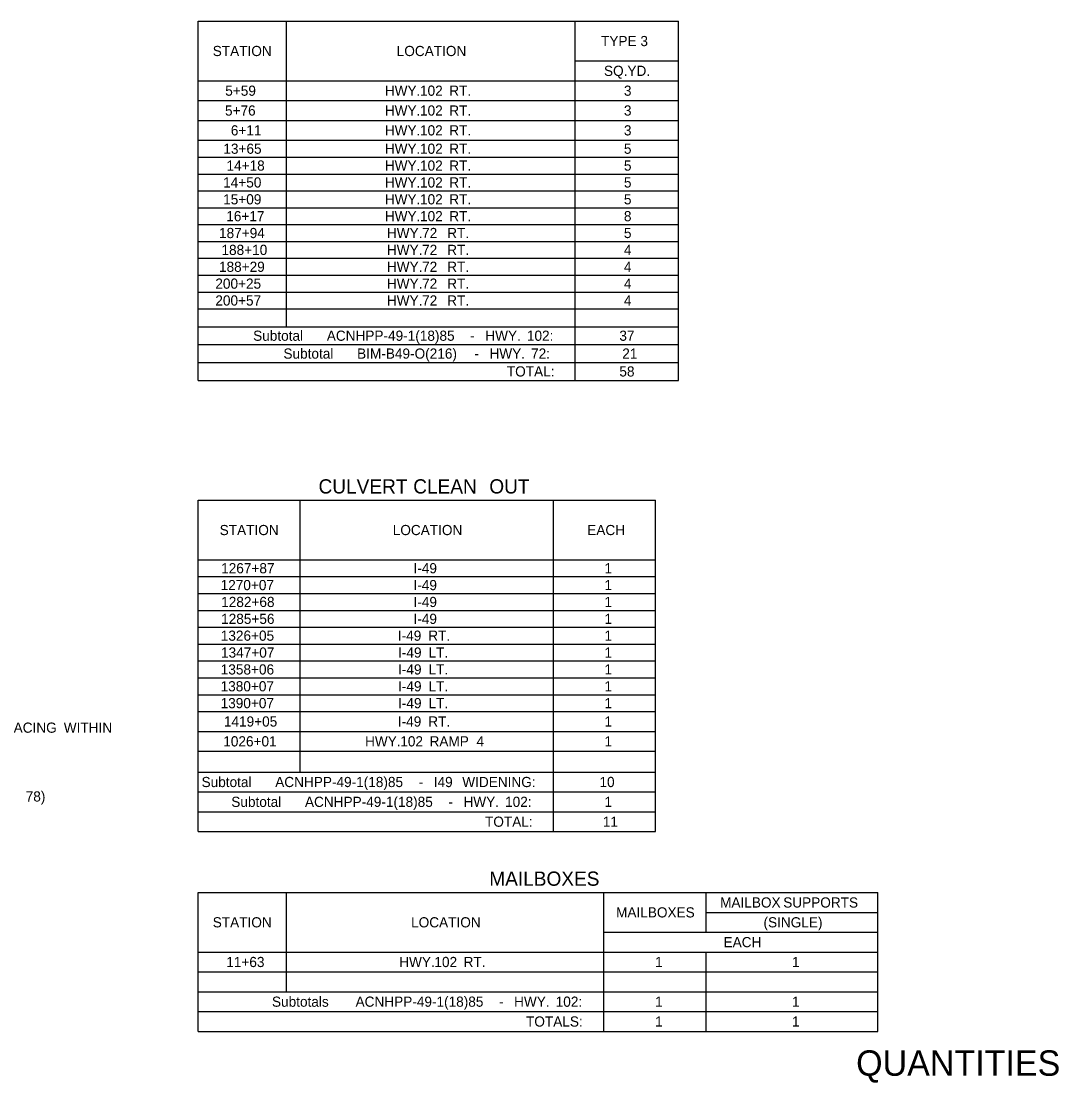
# Model space of a CAD drawing. Extents: x 1226605 to 1228152, y 151309 to 152316.
# Drawn here: x 1227621 to 1228130, y 151309 to 151831 of the extents above; entities that cross this region are included whole.
import ezdxf

# ---------------------------------------------------------------- set-up
doc = ezdxf.new("R2010")
doc.units = 0
doc.layers.add('R_Border Notes', color=7, linetype='Continuous')
doc.layers.add('R_Dimension', color=7, linetype='Continuous')

msp = doc.modelspace()

# ---------------------------------------------------------------- linework, layer by layer
at = {"layer": 'R_Dimension'}
for p, q in [((1227707.52, 151831.05), (1227943.47, 151831.05)), ((1227707.52, 151654.57), (1227707.52, 151831.05)), ((1227750.91, 151680.9), (1227750.91, 151831.05)), ((1227892.77, 151654.57), (1227892.77, 151831.05)), ((1227943.47, 151654.57), (1227943.47, 151831.05)), ((1227892.77, 151811.55), (1227943.47, 151811.55)), ((1227707.52, 151801.8), (1227943.47, 151801.8)), ((1227707.52, 151792.05), (1227943.47, 151792.05)), ((1227707.52, 151782.3), (1227943.47, 151782.3)), ((1227707.52, 151772.55), (1227943.47, 151772.55)), ((1227707.52, 151764.26), (1227943.47, 151764.26)), ((1227707.52, 151755.97), (1227943.47, 151755.97)), ((1227707.52, 151747.68), (1227943.47, 151747.68)), ((1227707.52, 151739.4), (1227943.47, 151739.4)), ((1227707.52, 151731.11), (1227943.47, 151731.11)), ((1227707.52, 151722.82), (1227943.47, 151722.82)), ((1227707.52, 151714.53), (1227943.47, 151714.53)), ((1227707.52, 151706.25), (1227943.47, 151706.25)), ((1227707.52, 151697.96), (1227943.47, 151697.96)), ((1227707.52, 151689.67), (1227943.47, 151689.67)), ((1227707.52, 151680.9), (1227943.47, 151680.9)), ((1227707.52, 151672.12), (1227943.47, 151672.12)), ((1227707.52, 151663.35), (1227943.47, 151663.35)), ((1227707.52, 151654.57), (1227943.47, 151654.57)), ((1227707.52, 151595.64), (1227932.26, 151595.64)), ((1227707.52, 151432.81), (1227707.52, 151595.64)), ((1227757.73, 151462.06), (1227757.73, 151595.64)), ((1227882.04, 151432.81), (1227882.04, 151595.64)), ((1227932.26, 151432.81), (1227932.26, 151595.64)), ((1227707.52, 151566.39), (1227932.26, 151566.39)), ((1227707.52, 151558.1), (1227932.26, 151558.1)), ((1227707.52, 151549.81), (1227932.26, 151549.81)), ((1227707.52, 151541.53), (1227932.26, 151541.53)), ((1227707.52, 151533.24), (1227932.26, 151533.24)), ((1227707.52, 151524.95), (1227932.26, 151524.95)), ((1227707.52, 151516.66), (1227932.26, 151516.66)), ((1227707.52, 151508.38), (1227932.26, 151508.38)), ((1227707.52, 151500.09), (1227932.26, 151500.09)), ((1227707.52, 151491.8), (1227932.26, 151491.8)), ((1227707.52, 151482.05), (1227932.26, 151482.05)), ((1227707.52, 151472.3), (1227932.26, 151472.3)), ((1227707.52, 151462.06), (1227932.26, 151462.06)), ((1227707.52, 151452.31), (1227932.26, 151452.31)), ((1227707.52, 151442.56), (1227932.26, 151442.56)), ((1227707.52, 151432.81), (1227932.26, 151432.81)), ((1227707.52, 151402.87), (1228041.46, 151402.87)), ((1227707.52, 151334.62), (1227707.52, 151402.87)), ((1227750.91, 151354.12), (1227750.91, 151402.87)), ((1227906.91, 151334.62), (1227906.91, 151402.87)), ((1227957.12, 151383.37), (1227957.12, 151402.87)), ((1228041.46, 151334.62), (1228041.46, 151402.87)), ((1227957.12, 151393.12), (1228041.46, 151393.12)), ((1227906.91, 151383.37), (1228041.46, 151383.37)), ((1227707.52, 151373.62), (1228041.46, 151373.62)), ((1227957.12, 151334.62), (1227957.12, 151373.62)), ((1227707.52, 151363.87), (1228041.46, 151363.87)), ((1227707.52, 151354.12), (1228041.46, 151354.12)), ((1227707.52, 151344.37), (1228041.46, 151344.37)), ((1227707.52, 151334.62), (1228041.46, 151334.62))]:
    msp.add_line(p, q, dxfattribs=at)

# ---------------------------------------------------------------- texts
at = {"layer": 'R_Border Notes'}
msp.add_text('QUANTITIES', height=12.5, dxfattribs=at).set_placement((1228030.78, 151312.82))
at = {"layer": 'R_Dimension'}
for s, height, p in [('TYPE', 5, (1227905.46, 151818.8)), (' 3', 5, (1227922.94, 151818.8)), ('STATION', 5, (1227714.7, 151813.92)), ('LOCATION', 5, (1227805.08, 151813.92)), ('SQ.YD.', 5, (1227906.9, 151804.17)), ('5+59', 5, (1227720.85, 151794.42)), ('HWY.', 5, (1227799.24, 151794.42)), (' 102', 5, (1227814.67, 151794.42)), (' RT.', 5, (1227829.04, 151794.42)), ('3', 5, (1227916.7, 151794.42)), ('5+76', 5, (1227720.73, 151784.67)), ('HWY.', 5, (1227799.24, 151784.67)), (' 102', 5, (1227814.67, 151784.67)), (' RT.', 5, (1227829.04, 151784.67)), ('3', 5, (1227916.7, 151784.67)), ('6+11', 5, (1227723.58, 151774.92)), ('HWY.', 5, (1227799.24, 151774.92)), (' 102', 5, (1227814.67, 151774.92)), (' RT.', 5, (1227829.04, 151774.92)), ('3', 5, (1227916.7, 151774.92)), ('13+65', 5, (1227719.92, 151765.9)), ('HWY.', 5, (1227799.24, 151765.9)), (' 102', 5, (1227814.67, 151765.9)), (' RT.', 5, (1227829.04, 151765.9)), ('5', 5, (1227916.7, 151765.9)), ('14+18', 5, (1227721.46, 151757.62)), ('HWY.', 5, (1227799.24, 151757.62)), (' 102', 5, (1227814.67, 151757.62)), (' RT.', 5, (1227829.04, 151757.62)), ('5', 5, (1227916.7, 151757.62)), ('14+50', 5, (1227719.82, 151749.33)), ('HWY.', 5, (1227799.24, 151749.33)), (' 102', 5, (1227814.67, 151749.33)), (' RT.', 5, (1227829.04, 151749.33)), ('5', 5, (1227916.7, 151749.33)), ('15+09', 5, (1227719.82, 151741.04)), ('HWY.', 5, (1227799.24, 151741.04)), (' 102', 5, (1227814.67, 151741.04)), (' RT.', 5, (1227829.04, 151741.04)), ('5', 5, (1227916.7, 151741.04)), ('16+17', 5, (1227721.34, 151732.75)), ('HWY.', 5, (1227799.24, 151732.75)), (' 102', 5, (1227814.67, 151732.75)), (' RT.', 5, (1227829.04, 151732.75)), ('8', 5, (1227916.7, 151732.75)), ('187+94', 5, (1227717.79, 151724.47)), ('HWY.', 5, (1227800.26, 151724.47)), (' 72', 5, (1227815.69, 151724.47)), (' RT.', 5, (1227828.02, 151724.47)), ('5', 5, (1227916.7, 151724.47)), ('188+10', 5, (1227718.99, 151716.18)), ('HWY.', 5, (1227800.26, 151716.18)), (' 72', 5, (1227815.69, 151716.18)), (' RT.', 5, (1227828.02, 151716.18)), ('4', 5, (1227916.7, 151716.18)), ('188+29', 5, (1227717.77, 151707.89)), ('HWY.', 5, (1227800.26, 151707.89)), (' 72', 5, (1227815.69, 151707.89)), (' RT.', 5, (1227828.02, 151707.89)), ('4', 5, (1227916.7, 151707.89)), ('200+25', 5, (1227715.98, 151699.6)), ('HWY.', 5, (1227800.26, 151699.6)), (' 72', 5, (1227815.69, 151699.6)), (' RT.', 5, (1227828.02, 151699.6)), ('4', 5, (1227916.7, 151699.6)), ('200+57', 5, (1227715.98, 151691.32)), ('HWY.', 5, (1227800.26, 151691.32)), (' 72', 5, (1227815.69, 151691.32)), (' RT.', 5, (1227828.02, 151691.32)), ('4', 5, (1227916.7, 151691.32)), ('Subtotal', 5, (1227734.54, 151674.01)), (' ACNHPP-49-1(18)85', 5, (1227768.87, 151674.01)), (' HWY.', 5, (1227846.75, 151674.01)), (' 102:', 5, (1227867.18, 151674.01)), ('37', 5, (1227914.46, 151674.01)), (' -', 5, (1227839.31, 151674.01)), ('Subtotal', 5, (1227749.43, 151665.23)), (' BIM-B49-O(216)', 5, (1227783.76, 151665.23)), (' HWY.', 5, (1227848.8, 151665.23)), (' 72:', 5, (1227869.23, 151665.23)), ('21', 5, (1227915.87, 151665.23)), (' -', 5, (1227841.35, 151665.23)), ('TOTAL:', 5, (1227859.19, 151656.46)), ('58', 5, (1227914.46, 151656.46)), ('CULVERT', 7, (1227766.67, 151598.96)), (' CLEAN', 7, (1227810.6, 151598.96)), (' OUT', 7, (1227847.97, 151598.96)), ('STATION', 5, (1227718.12, 151578.51)), ('LOCATION', 5, (1227803.13, 151578.51)), ('EACH', 5, (1227898.68, 151578.51)), ('1267+87', 5, (1227718.84, 151559.75)), ('I-49', 5, (1227813.33, 151559.75)), ('1', 5, (1227907.15, 151559.75)), ('1270+07', 5, (1227718.57, 151551.46)), ('I-49', 5, (1227813.33, 151551.46)), ('1', 5, (1227907.15, 151551.46)), ('1282+68', 5, (1227718.84, 151543.17)), ('I-49', 5, (1227813.33, 151543.17)), ('1', 5, (1227907.15, 151543.17)), ('1285+56', 5, (1227718.82, 151534.88)), ('I-49', 5, (1227813.33, 151534.88)), ('1', 5, (1227907.15, 151534.88)), ('1326+05', 5, (1227718.65, 151526.6)), ('I-49', 5, (1227805.63, 151526.6)), (' RT.', 5, (1227818.74, 151526.6)), ('1', 5, (1227907.15, 151526.6)), ('1347+07', 5, (1227718.77, 151518.31)), ('I-49', 5, (1227805.75, 151518.31)), (' LT.', 5, (1227818.86, 151518.31)), ('1', 5, (1227907.15, 151518.31)), ('1358+06', 5, (1227718.63, 151510.02)), ('I-49', 5, (1227805.75, 151510.02)), (' LT.', 5, (1227818.86, 151510.02)), ('1', 5, (1227907.15, 151510.02)), ('1380+07', 5, (1227718.57, 151501.73)), ('I-49', 5, (1227805.75, 151501.73)), (' LT.', 5, (1227818.86, 151501.73)), ('1', 5, (1227907.15, 151501.73)), ('1390+07', 5, (1227718.57, 151493.45)), ('I-49', 5, (1227805.75, 151493.45)), (' LT.', 5, (1227818.86, 151493.45)), ('1', 5, (1227907.15, 151493.45)), (' SPACING', 5, (1227606.11, 151481.39)), (' WITHIN', 5, (1227639.66, 151481.39)), ('1419+05', 5, (1227720.18, 151484.43)), ('I-49', 5, (1227805.63, 151484.43)), (' RT.', 5, (1227818.74, 151484.43)), ('1', 5, (1227907.15, 151484.43)), ('1026+01', 5, (1227719.87, 151474.68)), ('HWY.', 5, (1227789.53, 151474.68)), (' 102', 5, (1227804.97, 151474.68)), (' RAMP', 5, (1227819.34, 151474.68)), (' 4', 5, (1227842.41, 151474.68)), ('1', 5, (1227907.15, 151474.68)), ('Subtotal', 5, (1227709.21, 151454.69)), (' ACNHPP-49-1(18)85', 5, (1227743.54, 151454.69)), (' I49', 5, (1227821.42, 151454.69)), (' WIDENING:', 5, (1227835.43, 151454.69)), ('10', 5, (1227904.69, 151454.69)), (' -', 5, (1227813.98, 151454.69)), (' 78)', 5, (1227620.96, 151447.6)), ('Subtotal', 5, (1227723.82, 151444.94)), (' ACNHPP-49-1(18)85', 5, (1227758.15, 151444.94)), (' HWY.', 5, (1227836.02, 151444.94)), (' 102:', 5, (1227856.46, 151444.94)), ('1', 5, (1227907.15, 151444.94)), (' -', 5, (1227828.58, 151444.94)), ('TOTAL:', 5, (1227848.46, 151435.19)), ('11', 5, (1227906.32, 151435.19)), ('MAILBOXES', 7, (1227850.57, 151406.19)), ('MAILBOX', 5, (1227963.95, 151395.49)), (' SUPPORTS', 5, (1227993.09, 151395.49)), ('MAILBOXES', 5, (1227912.84, 151390.62)), ('STATION', 5, (1227714.7, 151385.74)), ('LOCATION', 5, (1227812.15, 151385.74)), ('(SINGLE)', 5, (1227985.27, 151385.74)), ('EACH', 5, (1227965.65, 151375.99)), ('11+63', 5, (1227721.34, 151366.24)), ('HWY.', 5, (1227806.31, 151366.24)), (' 102', 5, (1227821.74, 151366.24)), (' RT.', 5, (1227836.11, 151366.24)), ('1', 5, (1227932.01, 151366.24)), ('1', 5, (1227999.29, 151366.24)), ('Subtotals', 5, (1227743.8, 151346.74)), (' ACNHPP-49-1(18)85', 5, (1227783.01, 151346.74)), (' HWY.', 5, (1227860.89, 151346.74)), (' 102:', 5, (1227881.32, 151346.74)), ('1', 5, (1227932.01, 151346.74)), ('1', 5, (1227999.29, 151346.74)), (' -', 5, (1227853.45, 151346.74)), ('TOTALS:', 5, (1227868.6, 151336.99)), ('1', 5, (1227932.01, 151336.99)), ('1', 5, (1227999.29, 151336.99))]:
    msp.add_text(s, height=height, dxfattribs=at).set_placement(p)

doc.saveas('drawing.dxf')
